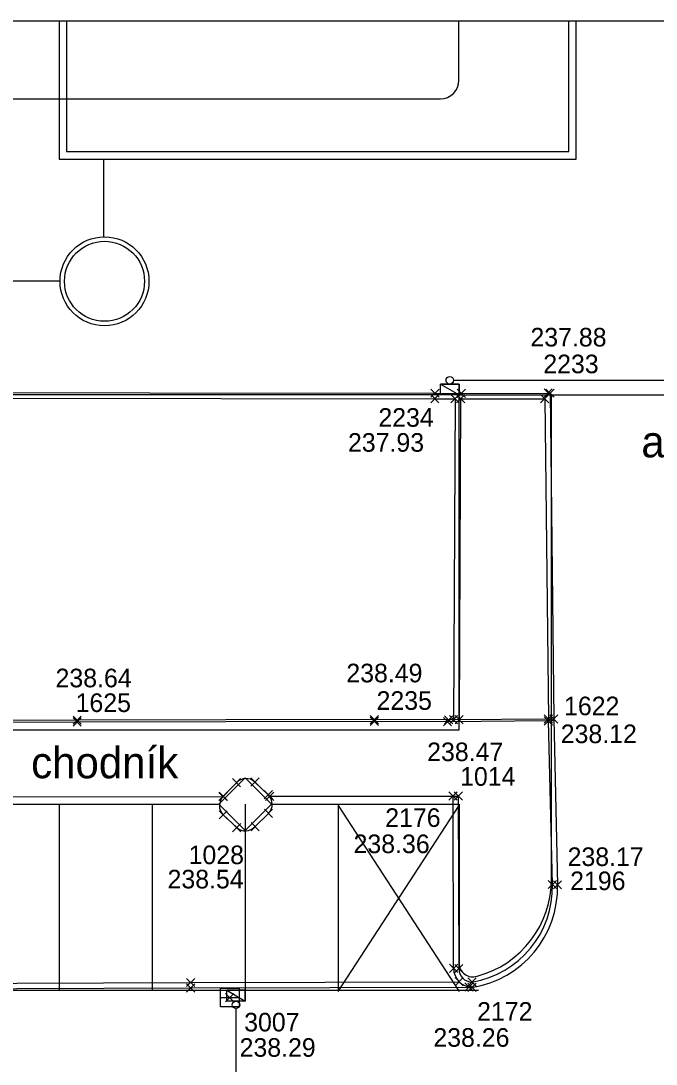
# Model space of a CAD drawing. Extents: x -264165 to -263733, y -1242319 to -1242245.
# Drawn here: x -263941.36 to -263924.28, y -1242272.97 to -1242244.94 of the extents above; entities that cross this region are included whole.
import ezdxf

# ---------------------------------------------------------------- set-up
doc = ezdxf.new("R2010")
doc.units = 0
for name, color, linetype in [('KFA_BOD_CISLO', 7, 'Continuous'), ('KFA_BOD_SYMBOL', 7, 'Continuous'), ('KFA_BOD_VYSKA', 7, 'Continuous'), ('KFA_SO_20-2_OBRUBNIKY_DOLNA_HRANA', 7, 'Continuous'), ('KFA_SO_20-2_OBRUBNIKY_HORNA_HRANA', 7, 'Continuous'), ('KFA_UV_BOD_CISLO', 7, 'Continuous'), ('KFA_UV_BOD_SYMBOL', 7, 'Continuous'), ('KFA_UV_BOD_VYSKA', 7, 'Continuous'), ('POPIS', 7, 'Continuous'), ('PROJEKT_OBRUBNIKY_KOMUNIKACIE', 7, 'Continuous'), ('PROJEKT_TDZ_VODOROVNE', 7, 'Continuous'), ('RAM_NA_TLAC_1-250', 7, 'Continuous'), ('SITUACIA_DSP_2D', 7, 'Continuous'), ('ULICNA_VPUST_POKLOP', 7, 'Continuous')]:
    doc.layers.add(name, color=color, linetype=linetype)

msp = doc.modelspace()

# ---------------------------------------------------------------- linework, layer by layer
at = {"layer": 'KFA_BOD_SYMBOL'}
for p, q in [((-263930.34, -1242255.049), (-263930.118, -1242254.828)), ((-263930.118, -1242255.049), (-263930.34, -1242254.828)), ((-263929.631, -1242255.056), (-263929.41, -1242254.835)), ((-263929.41, -1242255.056), (-263929.631, -1242254.835)), ((-263927.294, -1242255.046), (-263927.073, -1242254.826)), ((-263927.073, -1242255.046), (-263927.294, -1242254.826)), ((-263927.294, -1242255.046), (-263927.073, -1242254.826)), ((-263927.073, -1242255.046), (-263927.294, -1242254.826)), ((-263927.245, -1242255.049), (-263927.024, -1242254.829)), ((-263927.024, -1242255.049), (-263927.245, -1242254.829)), ((-263930.342, -1242255.198), (-263930.121, -1242254.978)), ((-263930.121, -1242255.198), (-263930.342, -1242254.978)), ((-263929.796, -1242255.2), (-263929.575, -1242254.978)), ((-263929.575, -1242255.2), (-263929.796, -1242254.978)), ((-263929.647, -1242255.2), (-263929.426, -1242254.978)), ((-263929.426, -1242255.2), (-263929.647, -1242254.978)), ((-263927.388, -1242255.2), (-263927.166, -1242254.978)), ((-263927.166, -1242255.2), (-263927.388, -1242254.978)), ((-263939.954, -1242263.836), (-263939.732, -1242263.616)), ((-263939.732, -1242263.836), (-263939.954, -1242263.616)), ((-263939.954, -1242263.887), (-263939.732, -1242263.666)), ((-263939.732, -1242263.887), (-263939.954, -1242263.666)), ((-263931.97, -1242263.819), (-263931.748, -1242263.597)), ((-263931.748, -1242263.819), (-263931.97, -1242263.597)), ((-263931.97, -1242263.869), (-263931.748, -1242263.647)), ((-263931.748, -1242263.869), (-263931.97, -1242263.647)), ((-263930, -1242263.876), (-263929.779, -1242263.654)), ((-263929.779, -1242263.876), (-263930, -1242263.654)), ((-263929.969, -1242263.826), (-263929.747, -1242263.605)), ((-263929.747, -1242263.826), (-263929.969, -1242263.605)), ((-263929.838, -1242263.825), (-263929.617, -1242263.603)), ((-263929.617, -1242263.825), (-263929.838, -1242263.603)), ((-263929.688, -1242263.823), (-263929.466, -1242263.603)), ((-263929.466, -1242263.823), (-263929.688, -1242263.603)), ((-263927.291, -1242263.806), (-263927.069, -1242263.585)), ((-263927.069, -1242263.806), (-263927.291, -1242263.585)), ((-263927.291, -1242263.856), (-263927.069, -1242263.634)), ((-263927.069, -1242263.856), (-263927.291, -1242263.634)), ((-263927.143, -1242263.805), (-263926.921, -1242263.583)), ((-263926.921, -1242263.805), (-263927.143, -1242263.583)), ((-263927.143, -1242263.805), (-263926.921, -1242263.583)), ((-263926.921, -1242263.805), (-263927.143, -1242263.583)), ((-263935.672, -1242265.516), (-263935.451, -1242265.296)), ((-263935.451, -1242265.516), (-263935.672, -1242265.296)), ((-263935.177, -1242265.498), (-263934.955, -1242265.276)), ((-263934.955, -1242265.498), (-263935.177, -1242265.276)), ((-263936.033, -1242265.887), (-263935.812, -1242265.667)), ((-263935.812, -1242265.887), (-263936.033, -1242265.667)), ((-263936.025, -1242265.88), (-263935.804, -1242265.66)), ((-263935.804, -1242265.88), (-263936.025, -1242265.66)), ((-263934.817, -1242265.839), (-263934.595, -1242265.617)), ((-263934.595, -1242265.839), (-263934.817, -1242265.617)), ((-263934.781, -1242265.879), (-263934.56, -1242265.657)), ((-263934.56, -1242265.879), (-263934.781, -1242265.657)), ((-263929.851, -1242265.873), (-263929.631, -1242265.653)), ((-263929.631, -1242265.873), (-263929.851, -1242265.653)), ((-263929.712, -1242265.873), (-263929.491, -1242265.653)), ((-263929.491, -1242265.873), (-263929.712, -1242265.653)), ((-263936.029, -1242266.377), (-263935.807, -1242266.157)), ((-263935.807, -1242266.377), (-263936.029, -1242266.157)), ((-263934.811, -1242266.34), (-263934.59, -1242266.12)), ((-263934.59, -1242266.34), (-263934.811, -1242266.12)), ((-263935.665, -1242266.722), (-263935.443, -1242266.502)), ((-263935.443, -1242266.722), (-263935.665, -1242266.502)), ((-263935.169, -1242266.694), (-263934.948, -1242266.474)), ((-263934.948, -1242266.694), (-263935.169, -1242266.474)), ((-263927.182, -1242268.249), (-263926.96, -1242268.029)), ((-263926.96, -1242268.249), (-263927.182, -1242268.029)), ((-263927.044, -1242268.258), (-263926.823, -1242268.038)), ((-263926.823, -1242268.258), (-263927.044, -1242268.038)), ((-263929.837, -1242270.502), (-263929.616, -1242270.281)), ((-263929.616, -1242270.502), (-263929.837, -1242270.281)), ((-263929.696, -1242270.505), (-263929.475, -1242270.285)), ((-263929.475, -1242270.505), (-263929.696, -1242270.285)), ((-263936.905, -1242270.883), (-263936.684, -1242270.661)), ((-263936.684, -1242270.883), (-263936.905, -1242270.661)), ((-263936.905, -1242271.028), (-263936.683, -1242270.806)), ((-263936.683, -1242271.028), (-263936.905, -1242270.806)), ((-263929.688, -1242270.863), (-263929.467, -1242270.641)), ((-263929.467, -1242270.863), (-263929.688, -1242270.641)), ((-263929.421, -1242271.005), (-263929.199, -1242270.785)), ((-263929.199, -1242271.005), (-263929.421, -1242270.785)), ((-263929.345, -1242271.014), (-263929.123, -1242270.792)), ((-263929.123, -1242271.014), (-263929.345, -1242270.792)), ((-263929.344, -1242270.872), (-263929.122, -1242270.65)), ((-263929.122, -1242270.872), (-263929.344, -1242270.65))]:
    msp.add_line(p, q, dxfattribs=at)
at = {"layer": 'KFA_SO_20-2_OBRUBNIKY_DOLNA_HRANA'}
for p, q in [((-263930.231, -1242255.088), (-263929.686, -1242255.089)), ((-263929.686, -1242255.089), (-263929.727, -1242263.714)), ((-263927.032, -1242263.694), (-263926.933, -1242268.148))]:
    msp.add_line(p, q, dxfattribs=at)
for points in [[(-263970.225, -1242255.029), (-263963.43, -1242255.035), (-263953.224, -1242255.054), (-263930.231, -1242255.088)], [(-263927.183, -1242254.936), (-263927.134, -1242254.939), (-263927.032, -1242263.694)], [(-263929.726, -1242270.391), (-263929.741, -1242265.763)], [(-263965.289, -1242270.846), (-263957.9, -1242270.825), (-263950.806, -1242270.811), (-263943.808, -1242270.801), (-263936.795, -1242270.772), (-263929.578, -1242270.752)], [(-263965.143, -1242270.987), (-263957.899, -1242270.977), (-263950.804, -1242270.956), (-263943.803, -1242270.944), (-263936.794, -1242270.917), (-263929.31, -1242270.895)]]:
    msp.add_lwpolyline(points, dxfattribs=at)
for centre, major_axis, ratio, start_param, end_param in [((-263929.65, -1242268.217), (2.482, -1.11), 0.999606, 5.286433, 6.729313), ((-263929.215, -1242270.392), (-0.294, -0.418), 0.999456, 5.322444, 6.858759)]:
    msp.add_ellipse(centre, major_axis=major_axis, ratio=ratio, start_param=start_param, end_param=end_param, dxfattribs=at)
at = {"layer": 'KFA_SO_20-2_OBRUBNIKY_HORNA_HRANA'}
for p, q in [((-263930.229, -1242254.938), (-263929.52, -1242254.945)), ((-263929.536, -1242255.089), (-263929.577, -1242263.713)), ((-263929.536, -1242255.089), (-263927.277, -1242255.089)), ((-263927.071, -1242268.139), (-263927.18, -1242263.745)), ((-263935.915, -1242265.77), (-263935.562, -1242265.406)), ((-263935.066, -1242265.387), (-263934.706, -1242265.728)), ((-263942.133, -1242265.787), (-263935.922, -1242265.777)), ((-263935.918, -1242266.267), (-263935.554, -1242266.612)), ((-263934.7, -1242266.23), (-263935.058, -1242266.584))]:
    msp.add_line(p, q, dxfattribs=at)
for points in [[(-263970.225, -1242254.882), (-263963.483, -1242254.892), (-263953.227, -1242254.91), (-263930.229, -1242254.938)], [(-263929.52, -1242254.945), (-263927.183, -1242254.936)], [(-263927.277, -1242255.089), (-263927.18, -1242263.695)], [(-263927.032, -1242263.694), (-263929.858, -1242263.715), (-263931.859, -1242263.708), (-263939.843, -1242263.726), (-263948.832, -1242263.749), (-263954.816, -1242263.759), (-263960.791, -1242263.777), (-263965.254, -1242263.802), (-263965.276, -1242265.854)], [(-263927.18, -1242263.745), (-263929.889, -1242263.765), (-263931.859, -1242263.758), (-263939.843, -1242263.776), (-263948.832, -1242263.799), (-263954.816, -1242263.809), (-263960.791, -1242263.827), (-263965.205, -1242263.852), (-263965.226, -1242265.854)], [(-263934.671, -1242265.768), (-263929.601, -1242265.763), (-263929.585, -1242270.395)]]:
    msp.add_lwpolyline(points, dxfattribs=at)
for centre, major_axis, ratio, start_param, end_param in [((-263935.305, -1242265.645), (-0.321, -0.145), 0.999085, 3.54274, 5.109586), ((-263935.667, -1242266.02), (-0.034, 0.351), 0.999242, 0.684117, 2.250423), ((-263934.953, -1242265.982), (-0.112, 0.336), 0.999809, 3.615093, 5.188028), ((-263935.321, -1242266.338), (0.108, -0.343), 0.999946, 5.271845, 6.79735), ((-263929.659, -1242268.206), (1.529, -2.091), 0.99928, 5.816835, 7.249076), ((-263929.226, -1242270.403), (-0.344, 0.103), 0.999351, 0.269711, 1.843256)]:
    msp.add_ellipse(centre, major_axis=major_axis, ratio=ratio, start_param=start_param, end_param=end_param, dxfattribs=at)
at = {"layer": 'KFA_UV_BOD_SYMBOL'}
for p, q in [((-263935.854, -1242271.289), (-263935.633, -1242271.069)), ((-263935.633, -1242271.289), (-263935.854, -1242271.069))]:
    msp.add_line(p, q, dxfattribs=at)
at = {"layer": 'PROJEKT_OBRUBNIKY_KOMUNIKACIE'}
for p, q in [((-263929.582, -1242246.53), (-263929.582, -1242244.935)), ((-263953.119, -1242247.03), (-263930.082, -1242247.03)), ((-263929.58, -1242254.982), (-263920.08, -1242254.982)), ((-263927.093, -1242267.983), (-263927.093, -1242254.982)), ((-263942.117, -1242265.982), (-263936.031, -1242265.982)), ((-263934.617, -1242265.982), (-263929.58, -1242265.983)), ((-263929.58, -1242265.983), (-263929.58, -1242270.257)), ((-263965.568, -1242270.982), (-263929.061, -1242270.982))]:
    msp.add_line(p, q, dxfattribs=at)
for points in [[(-263929.58, -1242254.982), (-263970.077, -1242254.982), (-263970.077, -1242263.982), (-263929.58, -1242263.982), (-263929.58, -1242254.982)], [(-263935.324, -1242265.275), (-263934.617, -1242265.982), (-263935.324, -1242266.689), (-263936.031, -1242265.982), (-263935.324, -1242265.275)]]:
    msp.add_lwpolyline(points, dxfattribs=at)
for centre, radius, start, end in [((-263930.082, -1242246.53), 0.5, 270, 359.9785), ((-263929.798, -1242267.992), 2.705, 285.1069, 0.1973), ((-263929.208, -1242270.25), 0.372, 181.1005, 288.0452)]:
    msp.add_arc(centre, radius, start, end, dxfattribs=at)
at = {"layer": 'PROJEKT_TDZ_VODOROVNE'}
for p, q in [((-263940.324, -1242265.982), (-263940.324, -1242270.982)), ((-263937.824, -1242265.982), (-263937.824, -1242270.982)), ((-263935.324, -1242265.982), (-263935.324, -1242270.982)), ((-263935.324, -1242265.982), (-263935.324, -1242270.982)), ((-263932.824, -1242265.982), (-263932.824, -1242270.982)), ((-263932.824, -1242271.014), (-263929.58, -1242266.014)), ((-263932.824, -1242266.014), (-263929.58, -1242271.014))]:
    msp.add_line(p, q, dxfattribs=at)
at = {"layer": 'RAM_NA_TLAC_1-250'}
msp.add_lwpolyline([(-264165.363, -1242244.935), (-263732.863, -1242244.935), (-263732.863, -1242319.185), (-264165.363, -1242319.185)], close=True, dxfattribs=at)
at = {"layer": 'SITUACIA_DSP_2D'}
for p, q in [((-263940.33, -1242244.935), (-263940.33, -1242248.649)), ((-263940.13, -1242244.935), (-263940.13, -1242248.449)), ((-263929.582, -1242246.53), (-263929.582, -1242244.935)), ((-263926.63, -1242248.449), (-263926.63, -1242244.935)), ((-263926.43, -1242248.649), (-263926.43, -1242244.935)), ((-263953.119, -1242247.03), (-263930.082, -1242247.03)), ((-263940.33, -1242248.649), (-263926.43, -1242248.649)), ((-263940.13, -1242248.449), (-263926.63, -1242248.449)), ((-263939.13, -1242248.649), (-263939.13, -1242250.737)), ((-263940.302, -1242251.932), (-263951.5, -1242251.932)), ((-263930.08, -1242254.692), (-263929.58, -1242254.692)), ((-263930.08, -1242254.982), (-263930.08, -1242254.692)), ((-263930.08, -1242254.692), (-263929.58, -1242254.982)), ((-263930.08, -1242254.692), (-263929.58, -1242254.982)), ((-263929.58, -1242254.692), (-263930.08, -1242254.692)), ((-263929.73, -1242254.592), (-263920.595, -1242254.592)), ((-263929.58, -1242254.692), (-263929.58, -1242254.982)), ((-263929.58, -1242254.982), (-263929.58, -1242254.692)), ((-263929.58, -1242254.982), (-263930.08, -1242254.982)), ((-263935.824, -1242270.983), (-263935.324, -1242270.983)), ((-263935.824, -1242271.273), (-263935.824, -1242270.983)), ((-263935.824, -1242270.983), (-263935.324, -1242271.273)), ((-263935.824, -1242270.983), (-263935.324, -1242271.273)), ((-263935.324, -1242270.983), (-263935.824, -1242270.983)), ((-263935.324, -1242270.983), (-263935.324, -1242271.273)), ((-263935.324, -1242271.273), (-263935.324, -1242270.983)), ((-263935.324, -1242271.273), (-263935.824, -1242271.273)), ((-263935.574, -1242271.473), (-263935.574, -1242283.187))]:
    msp.add_line(p, q, dxfattribs=at)
msp.add_lwpolyline([(-263929.58, -1242254.982), (-263970.077, -1242254.982), (-263970.077, -1242263.982), (-263929.58, -1242263.982), (-263929.58, -1242254.982)], dxfattribs=at)
msp.add_lwpolyline([(-263935.324, -1242265.275), (-263934.617, -1242265.982), (-263935.324, -1242266.689), (-263936.031, -1242265.982)], close=True, dxfattribs=at)
for centre, radius in [((-263939.107, -1242251.932), 1.195), ((-263939.107, -1242251.932), 1.075), ((-263929.83, -1242254.592), 0.1), ((-263935.574, -1242271.373), 0.1)]:
    msp.add_circle(centre, radius, dxfattribs=at)
msp.add_arc((-263930.082, -1242246.53), 0.5, 270, 359.9785, dxfattribs=at)
at = {"layer": 'ULICNA_VPUST_POKLOP'}
msp.add_line((-263935.743, -1242271.179), (-263935.743, -1242271.179), dxfattribs=at)
msp.add_lwpolyline([(-263935.993, -1242271.179), (-263935.993, -1242270.929), (-263935.493, -1242270.929), (-263935.493, -1242271.429), (-263935.993, -1242271.429), (-263935.993, -1242271.179), (-263935.493, -1242271.179)], dxfattribs=at)

# ---------------------------------------------------------------- texts
at = {"layer": 'KFA_BOD_CISLO'}
for s, p in [('2233', (-263927.315, -1242254.403)), ('2234', (-263931.747, -1242255.841)), ('2235', (-263931.796, -1242263.447)), ('1625', (-263939.884, -1242263.505)), ('1622', (-263926.758, -1242263.592)), ('1014', (-263929.551, -1242265.487)), ('2176', (-263931.563, -1242266.593)), ('1028', (-263936.847, -1242267.593)), ('2196', (-263926.593, -1242268.291)), ('2172', (-263929.095, -1242271.8))]:
    msp.add_text(s, height=0.5, dxfattribs=at).set_placement(p)
at = {"layer": 'KFA_BOD_VYSKA'}
for s, p in [('237.88', (-263927.661, -1242253.684)), ('237.93', (-263932.564, -1242256.512)), ('238.64', (-263940.423, -1242262.841)), ('238.49', (-263932.608, -1242262.708)), ('238.12', (-263926.847, -1242264.341)), ('238.47', (-263930.436, -1242264.825)), ('238.36', (-263932.414, -1242267.297)), ('238.17', (-263926.662, -1242267.643)), ('238.54', (-263937.413, -1242268.245)), ('238.26', (-263930.269, -1242272.5))]:
    msp.add_text(s, height=0.5, dxfattribs=at).set_placement(p)
at = {"layer": 'KFA_UV_BOD_CISLO'}
msp.add_text('3007', height=0.5, dxfattribs=at).set_placement((-263935.354, -1242272.088))
at = {"layer": 'KFA_UV_BOD_VYSKA'}
msp.add_text('238.29', height=0.5, dxfattribs=at).set_placement((-263935.477, -1242272.768))
at = {"layer": 'POPIS'}
for s, p in [('asfalt', (-263924.681, -1242256.663)), ('chodník', (-263941.079, -1242265.285))]:
    msp.add_text(s, height=0.8438, dxfattribs=at).set_placement(p)

doc.saveas('drawing.dxf')
